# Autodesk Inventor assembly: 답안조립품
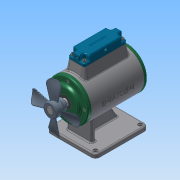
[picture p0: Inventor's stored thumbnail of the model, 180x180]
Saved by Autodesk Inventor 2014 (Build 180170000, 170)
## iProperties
Created: 2019-07
Part Number: 답안조립품
Document SubType Name: Assembly
Designer: net
Author: net
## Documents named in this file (19)
- C:\Users\net\Desktop\390704V1027\답안조립품.iam
- C:\Users\net\Desktop\390704V1027\뒤커버.ipt
- C:\Users\net\Desktop\390704V1027\멈춤나사 M4 x 5.ipt
- C:\Users\net\Desktop\390704V1027\베어링 6203.ipt
- C:\Users\net\Desktop\390704V1027\본체.ipt
- C:\Users\net\Desktop\390704V1027\볼트 M4 x 12.ipt
- C:\Users\net\Desktop\390704V1027\볼트 M4 x 16.ipt
- C:\Users\net\Desktop\390704V1027\부시.ipt
- C:\Users\net\Desktop\390704V1027\스프링 1.ipt
- C:\Users\net\Desktop\390704V1027\스프링 2.ipt
- C:\Users\net\Desktop\390704V1027\스프링 3.ipt
- C:\Users\net\Desktop\390704V1027\슬라이드.ipt
- C:\Users\net\Desktop\390704V1027\앞커버.ipt
- C:\Users\net\Desktop\390704V1027\오일실 17 30 8.ipt
- C:\Users\net\Desktop\390704V1027\축.ipt
- C:\Users\net\Desktop\390704V1027\키 5 x 5 x 18.ipt
- C:\Users\net\Desktop\390704V1027\팬날개.ipt
- 팬날개.ipt
- C:\Users\net\Desktop\390704V1027\헤더커버.ipt
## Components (1 placed, 1 different names)
1. 헤더커버:1 — 구동부
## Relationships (1: Angle 1)
- 구동부 [Angle]: 헤더커버:1
